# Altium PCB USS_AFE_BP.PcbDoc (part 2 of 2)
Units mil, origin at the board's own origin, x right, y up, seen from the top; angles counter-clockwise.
Board outline 2300 x 2500 mil, 4 copper layers (Top Layer, GND, PWR, Bottom Layer), stack 59 mil thick; 119 components, 70 nets, 303 pads, 68 vias.
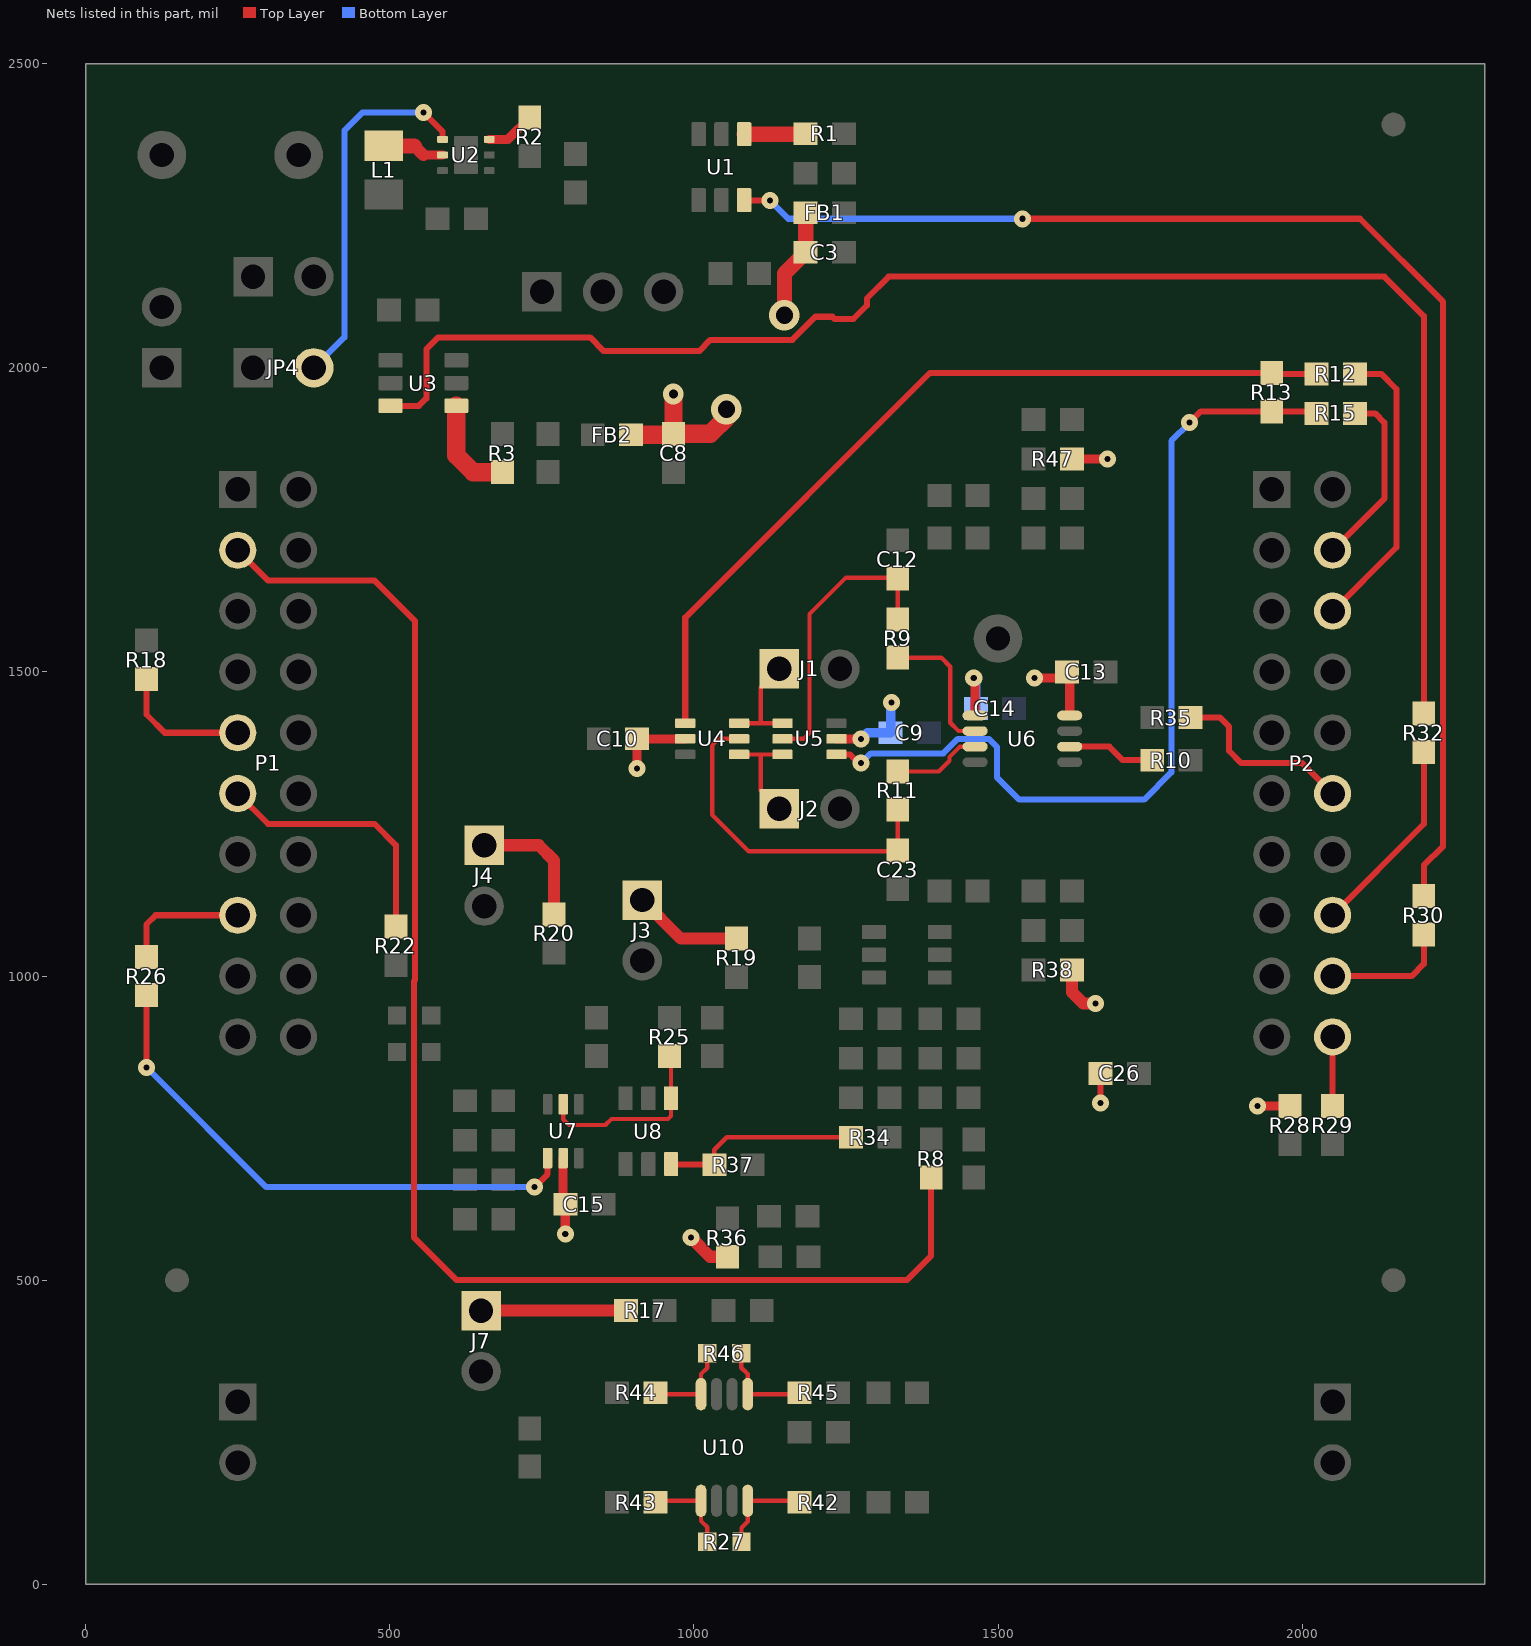
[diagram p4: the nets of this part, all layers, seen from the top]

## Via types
v1: diameter 28, hole 10, Top Layer to Bottom Layer, tented both sides, 55 vias
v2: diameter 34, hole 15, Top Layer to Bottom Layer, tented both sides, 7 vias
v3: diameter 50, hole 28, Top Layer to Bottom Layer, tented both sides, 4 vias
v4: diameter 19.68, hole 7.87, Top Layer to Bottom Layer, 2 vias

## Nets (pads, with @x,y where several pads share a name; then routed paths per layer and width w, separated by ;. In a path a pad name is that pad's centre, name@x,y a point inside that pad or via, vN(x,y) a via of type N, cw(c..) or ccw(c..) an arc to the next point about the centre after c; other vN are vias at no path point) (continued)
NetJ1_1: J1.1 U4.6 U5.4 | length 173.3
  Top Layer w7: U4.6@1074.29,1415.59 1110,1415.59 ; J1.1@1140,1505 1110,1475 1110,1415.59 ; U5.4@1145.71,1415.59 1110,1415.59
NetJ2_1: J2.1 U4.4 U5.6 | length 173.3
  Top Layer w7: U4.4@1074.29,1364.41 1110,1364.41 ; J2.1@1140,1275 1110,1305 1110,1364.41 ; U5.6@1145.71,1364.41 1110,1364.41
NetJP4_2: JP4.2 U2.4 | length 610.6
  Top Layer w10: v1(555.18,2419.88) 586.79,2388.27 U2.4@586.79,2375.48
  Bottom Layer w10: JP4.2@375.18,1999.88 425.18,2049.88 425.18,2389.88 455.18,2419.88 v1(555.18,2419.88)
NetL1_1: L1.1 U2.5 | length 102.8
  Top Layer w15: 555.18,2349.88 U2.5@586.79,2349.88
  Top Layer w20: 540.18,2364.88 555.18,2349.88
  Top Layer w25: L1.1@490.18,2364.88 540.18,2364.88
NetP1_3: P1.3 R8.1 | length 2378
  Top Layer w10: P1.3@250,1700 300,1650 475,1650 541.57,1583.43 541.57,993.49 540,991.91 540,570 610,500 1350,500 1390,540 R8.1@1390,668.5
NetP1_9: P1.9 R18.2 | length 220.9
  Top Layer w10: R18.2@100,1488.5 100,1430 130,1400 P1.9@250,1400
NetP1_11: P1.11 R22.2 | length 428.7
  Top Layer w10: P1.11@250,1300 300,1250 475,1250 510,1215 R22.2@510,1081.5
NetP1_15: P1.15 R26.2 | length 209.7
  Top Layer w10: R26.2@100,1031.5 100,1085 115,1100 P1.15@250,1100
NetP2_4: P2.4 R15.1 | length 299.9
  Top Layer w10: P2.4@2050,1700 2135,1785 2135,1910 2120,1925 R15.1@2086.5,1925
NetP2_6: P2.6 R12.1 | length 487.4
  Top Layer w10: P2.6@2050,1600 2155,1705 2155,1965 2130,1990 R12.1@2086.5,1990
NetP2_12: P2.12 R35.2 | length 318.7
  Top Layer w10: R35.2@1816.5,1425 1865,1425 1880,1410 1880,1370 1900,1350 2000,1350 P2.12@2050,1300 P2.12@2040,1300
NetP2_16: P2.16 R32.2 | length 330.6
  Top Layer w10: P2.16@2050,1100 2200,1250 R32.2@2200,1368.5
NetP2_18: P2.18 R30.2 | length 206.8
  Top Layer w10: P2.18@2050,1000 2180,1000 2200,1020 R30.2@2200,1068.5
NetP2_20: P2.20 R29.2 | length 113.5
  Top Layer w10: R29.2@2050,786.5 P2.20@2050,900
NetR1_2: R1.2 U1.1 | length 100.2
  Top Layer w25: U1.1@1082.58,2384.02 R1.2@1182.81,2384.02
NetR2_2: R2.2 U2.3 | length 81.5
  Top Layer w15: U2.3@663.56,2375.48 694.27,2375.48 R2.2@730.18,2411.38
NetR3_2: R3.2 U3.1 | length 168.9
  Top Layer w30: U3.1@609.31,1937.48 609.31,1855.75 636.67,1828.39 R3.2@685.18,1828.39
NetR9_1: R9.1 U6.2 | length 231.3
  Top Layer w7: R9.1@1335,1523.5 1406.5,1523.5 1421.37,1508.63 1421.37,1416.34 1434.92,1402.8 U6.2@1462.24,1402.8
NetR10_1: R10.1 U6.6 | length 144.9
  Top Layer w10: U6.6@1617.76,1377.2 1682.8,1377.2 1705,1355 R10.1@1753.5,1355
NetR11_1: R11.1 U6.3 | length 148.9
  Top Layer w7: R11.1@1335,1336.5 1402.5,1336.5 1420,1354 1420,1360 1437.2,1377.2 U6.3@1462.24,1377.2
  Top Layer w10: U6.3@1462.24,1377.2 U6.3@1462.24,1378.49
NetR25_2: R25.2 U7.5 U8.4 | length 308.8
  Top Layer w7: U7.5@785,789.29 785,764.68 794.68,755 855,755 855,755.71 864.29,765 957.4,765 962.4,770 U8.4@962.4,799.13 R25.2@962.4,866.1
NetR27_1: R27.1 R42.2 U10.8 | length 157.8
  Top Layer w7: R27.1@1078,70 1078,93 1088.38,103.38 U10.8@1088.38,137.4 1171.1,137.4 R42.2@1173.5,135
NetR27_2: R27.2 R43.1 U10.5 | length 147.8
  Top Layer w7: R43.1@936.5,135 938.9,137.4 U10.5@1011.61,137.4 1011.61,104.37 1022,93.99 R27.2@1022,70
NetR34_1: R34.1 R37.2 U8.3 | length 329.5
  Top Layer w7: R37.2@1033.5,690 1033.5,714.5 1054,735 R34.1@1258.5,735
  Top Layer w10: U8.3@962.4,690.87 963.27,690 R37.2@1033.5,690
NetR44_1: R44.1 R46.2 U10.4 | length 147.8
  Top Layer w7: R44.1@936.5,315 938.9,312.6 U10.4@1011.61,312.6 1011.61,345.63 1021.87,355.89 R46.2@1021.87,380
NetR45_2: R45.2 R46.1 U10.1 | length 157.9
  Top Layer w7: R46.1@1077.87,380 1077.87,356.15 1088.38,345.63 U10.1@1088.38,312.6 1171.1,312.6 R45.2@1173.5,315
RX_GAIN: R26.1 U7.1 | length 894.7
  Top Layer w10: v1(100,850) R26.1@100,968.5 ; v1(738,653) 759.41,674.41 U7.1@759.41,700.71
  Bottom Layer w10: v1(100,850) 297,653 v1(738,653)
RX_MUX: R12.2 R13.1 U4.1 | length 1378.7
  Top Layer w10: U4.1@985.71,1415.59 985.71,1589.29 1387.91,1991.5 R13.1@1950,1991.5 1951.5,1990 R12.2@2023.5,1990
RX_PWRSW: R32.1 U3.6 | length 2542.8
  Top Layer w10: U3.6@501.04,1937.48 547.77,1937.48 560.18,1949.88 560.18,2030.75 579.31,2049.88 829.29,2049.88 851.67,2027.51 1008.69,2027.51 1027.06,2045.88 1161.75,2045.88 1199.75,2083.88 1227.61,2083.88 1230.98,2080.51 1262.36,2080.51 1284.55,2102.7 1284.55,2114.25 1320.18,2149.88 2135.12,2149.88 2200,2085 R32.1@2200,1431.5
RX_SIGNAL: C23.1 R11.2 U4.5 | length 560.9
  Top Layer w7: U4.5@1074.29,1390 1040,1390 1030,1380 1030,1265 1090,1205 1333.5,1205 C23.1@1335,1206.5 R11.2@1335,1273.5
TX_MUX: R13.2 R15.2 U5.1 | length 1468.5
  Top Layer w10: U5.1@1234.88,1365 U5.1@1234.29,1364.41 1256.46,1364.41 1270.87,1350 v1(1275,1350) ; v1(1815,1910) 1833.5,1928.5 R13.2@1950,1928.5 2020,1928.5 R15.2@2023.5,1925
  Bottom Layer w10: v1(1275,1350) 1291.02,1366.02 1410,1366.02 1433.98,1390 1485,1390 1498.13,1376.87 1498.13,1326.87 1535,1290 1740,1290 1785,1335 1785,1880 v1(1815,1910)
TX_PWRSW: R30.1 U1.6 | length 2207.1
  Top Layer w10: U1.6@1083.44,2274.88 v1(1125.18,2274.88) ; v1(1540,2245) 2095,2245 2231.57,2108.43 2231.57,1213.49 2200,1181.91 R30.1@2200,1131.5
  Bottom Layer w10: v1(1125.18,2274.88) 1155.06,2245 v1(1540,2245)
TX_SIGNAL: C12.1 R9.2 U5.5 | length 478.8
  Top Layer w7: U5.5@1145.71,1390 1180,1390 1190,1400 1190,1595 1250,1655 C12.1@1333.5,1655 ; R9.2@1335,1586.5 C12.1@1335,1653.5
VCC-RX: C8.1 C13.2 C15.1 C26.2 FB2.2 J3.1 J4.1 J7.1 R17.2 R19.2 R20.2 R28.1 R36.2 R38.2 R47.2 U6.8 U7.2 | length 1446.4
  Top Layer w10: v1(1668.5,791.5) C26.2@1668.5,840
  Top Layer w15: C15.1@785,628.5 U7.2@785,700.71 ; v1(788.5,575.98) C15.1@788.5,625 ; v1(1560,1490) 1603.5,1490 C13.2@1613.5,1500 1617.76,1495.75 U6.8@1617.76,1428.39 ; R47.2@1621.5,1850 v1(1680,1850) ; v1(1926.5,786.5) R28.1@1980,786.5
  Top Layer w20: J7.1@650,450 R17.2@888.5,450 ; J4.1@655,1215 745,1215 770,1190 R20.2@770,1101.5 ; J3.1@915,1125 978.5,1061.5 R19.2@1070,1061.5 ; v1(995,570) 1026.5,538.5 R36.2@1055,538.5 ; R38.2@1621.5,1008.68 1621.5,973.5 1640,955 v1(1660,955)
  Top Layer w30: FB2.2@896.67,1889.88 C8.1@964.98,1889.88 ; v2(966.18,1956.88) 966.47,1956.59 C8.1@966.47,1891.38 1026.67,1891.38 1053.18,1917.88 v3(1053.18,1931.88)
VCC-TX: C3.1 C9.1 C10.1 C14.1 FB1.2 U4.2 U5.2 U6.1 | length 572.2
  Top Layer w15: v1@904,1339 v1(906.5,1341.5) C10.1@906.5,1390 U4.2@985.71,1390 ; U5.2@1234.29,1390 v1(1275,1390) ; v1(1460,1490) 1462.24,1487.76 U6.1@1462.24,1428.39
  Top Layer w25: v3(1148.68,2086.38) 1148.68,2154.88 C3.1@1183.68,2189.88 FB1.2@1183.68,2254.88
  Bottom Layer w15: v1(1275,1390) 1285,1400 C9.1@1323.5,1400 1323.5,1448.5 v1(1325,1450) ; v1(1460,1490) 1463.5,1486.5 C14.1@1463.5,1440
pads on no net: FID1.1 FID2.1 FID3.1 LBL1.0 P1.5 P1.6 P1.7 P1.8 P1.10 P1.12 P1.13 P1.17 P1.18 P1.19 P1.20 P2.1 P2.3 P2.5 P2.7 P2.8 P2.9 P2.10 P2.11 P2.13 P2.14 P2.15 P2.17 P2.19 U1.3 U2.7@625.18,2332.17 U2.7@625.18,2367.6 U3.3

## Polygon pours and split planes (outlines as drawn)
VCC-RX on PWR "VCC-RX_L03_P012" (solid, remove dead copper, pour order 12): 25.26,2475 2274.74,2475 2274.74,25.26 25.26,25.26
VCC-TX on PWR "VCC-TX_L03_P010" (solid, remove dead copper, pour order 10): 807.5,1300 1510,1300 1510,1600 1510,2140 1100,2140 1100,1600 807.5,1600
GND on GND "GND_L02_P002" (solid, pour order 2): 25,2475 2275,2475 2275,25 25,25

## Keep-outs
Keep-Out Layer:
  pour cut-out: 1267.3,1185 1267.3,975 1432.68,975 1435,977.32 1435,1185
  pour cut-out: 1340,973.98 1340,836.46 1478.71,836.46 1480,837.75 1480,975 1341.02,975
  pour cut-out: 854.13,827.68 854.13,662.32 985,662.32 985,827.68
  pour cut-out: 985,725 1070,725 1070,661.46 985,661.46
  pour cut-out: 935,827.68 935,900 985,900 985,827.68
  pour cut-out: 905,355 905,270 1200,270 1200,355
  pour cut-out: 905,175 905,95 1205,95 1205,175
  pour cut-out: 997.87,404 997.87,355 1101.87,355 1101.87,404
  pour cut-out: 998,95 998,46 1102,46 1102,95
  pour cut-out: 1363.54,1185 1363.54,1295 1300,1295 1300,1220 1218.58,1220 1218.58,1555 1100.99,1555 1010,1484.86 1010,1260 1085,1185
  pour cut-out: 1300,1680 1300,1825 1430,1825 1430,1680
  lines w15: -7.5,0 ccw(c0,0) 0,-7.5 ; -7.5,0 ccw(c0,0) 0,-7.5 ; -7.5,0 -7.5,2500 ; -7.5,2500 cw(c0,2500) 0,2507.5 ; -7.5,2500 cw(c0,2500) 0,2507.5 ; 0,-7.5 2300,-7.5 ; 0,2507.5 2300,2507.5 ; 2300,-7.5 ccw(c2300,0) 2307.5,0 ; 2300,-7.5 ccw(c2300,0) 2307.5,0 ; 2300,2507.5 cw(c2300,2500) 2307.5,2500 ; 2300,2507.5 cw(c2300,2500) 2307.5,2500 ; 2307.5,0 2307.5,2500
  text ".Layer_Name" at 577,-858.49 h60

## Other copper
Top Layer:
  text ".Layer_Name" at 577,-858.49 h60
GND:
  pour cut-out: 1170,1555 1170,1600 1250,1680 1363.54,1680 1363.54,1565 1300,1565 1300,1630 1295,1635 1250,1635 1220,1605 1220,1555
  text ".Layer_Name" at 577,-858.49 h60
PWR:
  pour cut-out: 1170,1555 1170,1600 1250,1680 1363.54,1680 1363.54,1565 1300,1565 1300,1630 1295,1635 1250,1635 1220,1605 1220,1555
  text ".Layer_Name" at 577,-858.49 h60
Bottom Layer:
  text ".Layer_Name" at 577,-858.49 h60

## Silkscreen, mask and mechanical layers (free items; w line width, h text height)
Top Overlay:
  lines w10: 965,1290 1030,1290 1085,1345 1140,1345
  text "3V3" at 75.18,2424.88 h40
  text "GND" at 300.18,2424.88 h40
  text "USS-AFE-BP" at 1590,2380 h40
  text ".PCB_Rev" at 1615,2300 h40
  text "5VTX" at 321.18,2213.88 h30
  text "|5VTX|" at 845.18,2194.88 h30
  text "|3V3TX|" at 700.18,2014.88 h30
  text "5VTX" at 330,1900 h30
  text "1" at 155,1780 h40
  text "21" at 400.01,1780 h40
  text "40" at 1835,1780 h40
  text "20" at 2100,1780 h40
  text "2" at 170,1685 h40
  text "22" at 400.01,1685 h40
  text "39" at 1840,1680 h40
  text "19" at 2100,1680 h40
  text "3" at 170,1580 h40
  text "23" at 400,1580 h40
  text "38" at 1840,1580 h40
  text "18" at 2100,1580 h40
  text "X1" at 1100,1565 h60
  text "GND" at 1180,1565 h60
  text "4" at 170,1480 h40
  text "24" at 400,1480 h40
  text "17" at 2100,1480 h40
  text "37" at 1900.01,1475 h40 r90
  text "5" at 170,1380 h40
  text "25" at 400,1380 h40
  text "16" at 2100,1380 h40
  text "36" at 1900.01,1370 h40 r90
  text "6" at 170,1280 h40
  text "26" at 400,1280 h40
  text "15" at 2100,1280 h40
  text "35" at 1905,1265 h40 r90
  text "7" at 170,1185 h40
  text "27" at 400,1185 h40
  text "34" at 1840,1180 h40
  text "14" at 2100,1180 h40
  text "X2" at 1110,1175 h60
  text "GND" at 1180,1175 h60
  text "8" at 170,1080 h40
  text "28" at 400,1080 h40
  text "33" at 1840,1080 h40
  text "13" at 2100,1080 h40
  text "9" at 170,980 h40
  text "29" at 395,980 h40
  text "32" at 1840,980 h40
  text "12" at 2100,980 h40
  text "10" at 140,880 h40
  text "30" at 395,880 h40
  text "31" at 1840,880 h40
  text "11" at 2100,880 h40
  text "GND" at 2130,285 h40
  text "GND" at 60,280 h40
  text "J5" at 310,230 h72.83
  text "J6" at 1920,230 h72.83
  text "GND" at 65,185 h40
  text "GND" at 2130,170 h40
  text ".Layer_Name" at 577,-858.49 h60
Bottom Overlay:
  text ".Layer_Name" at 577,-858.49 h60
Top Paste:
  text ".Layer_Name" at 577,-858.49 h60
Bottom Paste:
  text ".Layer_Name" at 577,-858.49 h60
Top Solder:
  text ".Layer_Name" at 577,-858.49 h60
  text ".Layer_Name" at 577,-858.49 h60
Bottom Solder:
  text ".Layer_Name" at 577,-858.49 h60
Drill Guide:
  text ".Layer_Name" at 577,-858.49 h60
M1 Board Outline:
  the board outline again, w10
  text ".Layer_Name" at 577,-858.49 h60
M2 Board Dimensions:
  rectangle: 125,-400 500,-275
  rectangle: 0,-275 125,-150
  lines w7: 0,-275 1000,-275 ; 125,-400 125,-150 ; 250,-400 250,-150 ; 500,-400 500,-150 ; 750,-400 750,-150 ; 0,-400 0,-150 1000,-150 1000,-400 0,-400
  text ".Layer_Name" at 577,-858.49 h60
M3 3D STEP Top:
  text ".Layer_Name" at 577,-858.49 h60
M4 3D STEP Bottom:
  text ".Layer_Name" at 577,-858.49 h60
M5 Assembly Top:
  lines w10: -292,-930.17 6308,-930.17 ; -292,-726.83 6310,-726.83 ; -292,-523.5 -292,-1133.5 3713,-1133.5 6310,-1133.5 6310,-523.5 -291.5,-523.5 -291.5,-1133.5 1284,-1133.5 ; 2173,-1133.5 2173,-523.5 ; 3440,-726.83 3440,-523.5 ; 4280,-726.83 4280,-523.5 ; 4902,-1140 4902,-937.17
  text "COMPONENTS MARKED 'DNP' SHOULD NOT BE POPULATED." at 1153.5,-318.5 h60
  text "ASSEMBLY VARIANT:" at 1153,-434 h60
  text ".VariantName" at 2189,-434 h60
  text "PCB VIEWED FROM TOP SIDE" at -228.5,-655.67 h60
  text "BOARD #:" at 2248,-655.67 h60
  text ".PRJ_Number" at 2793.5,-655.67 h60
  text "REV:" at 3638,-655.67 h60
  text ".PCB_Rev" at 3929.5,-655.67 h60
  text "SVN REV:" at 4476,-655.67 h60
  text ".VersionControl_RevNumber" at 4982,-655.67 h60
  text "TID #:" at 2248,-859 h60
  text ".TID" at 2793.5,-859 h60
  text "PLOT NAME =" at -228.5,-1064.34 h60
  text ".plot_File_Name" at 577,-1064.34 h60
  text "GENERATED    :" at 2250,-1064.34 h60
  text ".Print_Date" at 3119.5,-1064.34 h60
  text ".Print_Time" at 3848.5,-1064.34 h60
  text "TEXAS INSTRUMENTS" at 5113,-1064.34 h60
M6 Assembly Bottom:
  lines w10: -292.5,-727.33 6309.5,-727.33 ; -290.5,-930.67 6309.5,-930.67 ; 1115.5,-1140.5 1115.5,-937.67 ; 1737.5,-727.33 1737.5,-524 ; 2577.5,-727.33 2577.5,-524 ; 3844.5,-1134 3844.5,-524 ; 4733.5,-1134 6309,-1134 6309,-524 -292.5,-524 -292.5,-1134 2304.5,-1134 6309.5,-1134 6309.5,-524
  text "COMPONENTS MARKED 'DNP' SHOULD NOT BE POPULATED." at 6102,-318 h60
  text ".VariantName" at 5058,-434 h60
  text "ASSEMBLY VARIANT:" at 6097,-434 h60
  text ".VersionControl_RevNumber" at 1035.5,-656.17 h60
  text "SVN REV:" at 1541.5,-656.17 h60
  text ".PCB_Rev" at 2088,-656.17 h60
  text "REV:" at 2379.5,-656.17 h60
  text ".PRJ_Number" at 3224,-656.17 h60
  text "BOARD #:" at 3769.5,-656.17 h60
  text "PCB VIEWED FROM BOTTOM SIDE" at 6246,-656.17 h60
  text ".TID" at 3224,-859.5 h60
  text "TID #:" at 3769.5,-859.5 h60
  text "TEXAS INSTRUMENTS" at 904.5,-1064.84 h60
  text ".Print_Time" at 2169,-1064.84 h60
  text ".Print_Date" at 2898,-1064.84 h60
  text "GENERATED    :" at 3767.5,-1064.84 h60
  text ".plot_File_Name" at 5440.5,-1064.84 h60
  text "PLOT NAME =" at 6246,-1064.84 h60
M9 Title Sheet:
  drawing of 57 lines, arcs and shapes, not listed
  text "1" at 739.84,8036.5 h70
  text "2" at 3235.5,8036.5 h70
  text "3" at 5724.84,8036.5 h70
  text "4" at 8231.51,8036.5 h70
  text "5" at 10730.5,8036.5 h70
  text "6" at 13235.5,8036.5 h70
  text "A" at -416.5,6893.5 h70
  text "A" at 14383.5,6893.5 h70
  text "B" at -416.5,4513.5 h70
  text "B" at 14383.5,4513.5 h70
  text "C" at -416.5,2138.5 h70
  text "C" at 14383.5,2138.5 h70
  text "PROJECT TITLE:" at 11343.5,277.5 h45
  text ".PRJ_Title" at 11393.5,144.17 h70
  text "DESIGNED FOR:" at 11343.5,-23.5 h45
  text ".PRJ_Customer" at 11393.5,-163.5 h70
  text "D" at -416.5,-231.5 h70
  text "D" at 14383.5,-231.5 h70
  text "FILE NAME:" at 11343.5,-323.5 h45
  text ".PCB_File_Name_No_Path" at 11393.5,-443.5 h70
  text "Texas Instruments (TI) and/or its licensors do not warrant the accuracy or completeness of this specification" at 6374,-605.34 h45
  text "ENGINEER:" at 11343.5,-613.5 h45
  text "LAYOUT BY:" at 12848.5,-613.5 h45
  text "or any information contained therein. TI and/or its licensors do not warrant that this design will meet" at 6329.01,-718 h45
  text ".PRJ_Engineer" at 11393.5,-768.49 h70
  text ".PCB_Layout" at 12899,-768.49 h70
  text "the specifications, will be suitable for your application or fit for any particular purpose, or will operate in" at 6329.01,-830.67 h45
  text ".Layer_Name" at 577,-858.49 h60
  text "ALTIUM DESIGNER VERSION:" at 12848.5,-923.5 h45
  text "an implementation. TI and/or its licensors do not warrant that the design is production worthy. You should" at 6329.01,-943.33 h45
  text "completely validate and test your design implementation to confirm the system functionality for your application." at 6374,-1056 h45
  text ".print_Scale" at 11393.5,-1056.83 h70
  text ".Application_BuildNumber" at 12899,-1056.83 h70
  text "1" at 739.84,-1263.5 h70
  text "2" at 3235.5,-1263.5 h70
  text "3" at 5724.84,-1263.5 h70
  text "4" at 8231.51,-1263.5 h70
  text "5" at 10730.5,-1263.5 h70
  text "6" at 13235.5,-1263.5 h70
M10 Fab Notes:
  drawing of 185 lines, arcs and shapes, not listed
  text "DESIGN INFORMATION" at 12381.02,5910 h60
  text "MIN. TRACK WIDTH:" at 11736.46,5730 h60
  text "7" at 12832.7,5730 h60
  text "MIL" at 12987.46,5730 h60
  text "MIN. CLEARANCE:" at 11736.46,5598 h60
  text "0.2" at 12772.7,5598 h60
  text "mm" at 12987.46,5598 h60
  text "MIN. VIA PAD SIZE:" at 11736.46,5466 h60
  text "24" at 12802.71,5466 h60
  text "MIL" at 12987.46,5466 h60
  text "0.05mm (2MIL)" at 12431.46,5324.29 h60
  text "MINIMUM ANNULAR RING" at 11407.23,5320 h60
  text "EXTERNAL" at 13139.46,5320 h60
  text "PER" at 11607.23,5202 h60
  text "IPC-D-275 CLASS 2 LEVEL C" at 11827.23,5202 h60
  text "MIL, HOLES" at 13315.46,5089.71 h60
  text "+/-" at 12923,5089 h60
  text "+/-" at 13777,5089 h60
  text "REGISTRATION TOLERANCES:" at 11407.23,5084 h60
  text "METAL" at 12607,5084 h60
  text "5" at 13183.2,5084 h60
  text "3" at 14016.2,5084 h60
  text "MIL" at 14132.46,5084 h60
  text "MATERIAL:" at 11332.46,4874.54 h60
  text "FR-4 High Tg" at 12318.9,4734.21 h60
  text "FR-408" at 11753.46,4725.64 h60
  text "X" at 12165.46,4725.64 h60
  text "OTHER" at 13241.46,4725.64 h60
  text "62 MIL (1.6mm) +/-10%" at 12073.56,4562.92 h60
  text "THICKNESS:" at 11407.23,4558.64 h60
  text "X" at 11945.4,4558.64 h60
  text "OTHER" at 13358.46,4558.64 h60
  text "TOLERANCE:" at 11407.23,4400.64 h60
  text "X" at 12246.53,4400.64 h60
  text "ANSI IPC-6012 TYPE 3 CLASS 2" at 12433.48,4400.64 h60
  text "OTHER +/-" at 12433.46,4244.64 h60
  text "BOW & TWIST:" at 11407.23,4087.64 h60
  text "X" at 12246.53,4087.64 h60
  text "ANSI IPC-6012 TYPE 3 CLASS 2" at 12433.48,4087.64 h60
  text "OTHER +/-" at 12433.46,3929.13 h60
  text "DRILLING:" at 11332.46,3790.64 h60
  text "REFERENCE:" at 11407.23,3673.64 h60
  text "X" at 12055.46,3673.64 h60
  text "AS SHOWN" at 12242.46,3673.64 h60
  text "X" at 12956.46,3673.64 h60
  text "NC_DRILL FILES" at 13093.46,3673.64 h60
  text "PTH MIN COPPER THICKNESS:" at 11407.23,3515.64 h60
  text "X" at 12757.46,3515.64 h60
  text "1MIL" at 12894.46,3515.64 h60
  text "OTHER" at 13391.46,3515.64 h60
  text "BOARD FINISH:" at 11332.46,3356.64 h60
  text "SILKSCREEN:" at 11487.68,3238.64 h60
  text "X" at 12436.46,3238.64 h60
  text "TOP" at 12562.46,3238.64 h60
  text "X" at 12946.46,3238.64 h60
  text "BOTTOM" at 13073.46,3238.64 h60
  text "SILKSCREEN COLOR:" at 11487.68,3071.64 h60
  text "X" at 12435.42,3071.64 h60
  text "WHITE" at 12562.46,3071.64 h60
  text "OTHER" at 13073.46,3071.64 h60
  text "SOLDER RESIST COLOR:" at 11487.68,2901.64 h60
  text "GREEN" at 12182.46,2742.44 h60
  text "BLUE" at 12773.46,2742.44 h60
  text "RED" at 13311.46,2742.44 h60
  text "X" at 12650,2735 h60
  text "IMMERSION GOLD (ENIG)" at 12393.46,2553.92 h60
  text "ENEPIG" at 13731,2550.64 h60
  text "SURFACE FINISH:" at 11332.46,2549.64 h60
  text "X" at 12206.51,2549.64 h60
  text "IMM. TIN/SILVER OR EQUIV" at 11662,2392.64 h60
  text "OTHER" at 13093.46,2392.64 h60
  text "ARRAY/PANEL:" at 11332.46,2213.64 h60
  text "CUT AND TRIM PER MECH LAYER 1" at 12393.46,2209.35 h60
  text "N.C. ROUTE" at 12393.46,2057.64 h60
  text "X" at 13072.46,2057.64 h60
  text "V. SCORE" at 13259.46,2057.64 h60
  text "CERTIFICATION:" at 11332.46,1920.64 h60
  text "MATERIALS AND WORKMANSHIP FOR ALL PCBS" at 12057.46,1920.64 h60
  text "TO MEET OR EXCEED THE REQUIREMENTS OF:" at 12057.46,1822.64 h60
  text "X" at 11683.96,1686.13 h60
  text "ANSI IPC-A-600F CLASS ->" at 11822.96,1686.13 h60
  text "X" at 13462.02,1686.13 h60
  text "2" at 13580.96,1686.14 h60
  text "1" at 13265.96,1684.64 h60
  text "3" at 13934.96,1684.64 h60
  text "X" at 11686.02,1526.64 h60
  text "UL 94V-0" at 11822.96,1526.64 h60
  text "X" at 12498.02,1526.64 h60
  text "RoHS" at 12634.96,1526.64 h60
  text "OTHER" at 13279.36,1526.64 h60
  text "PER ORDER" at 13676.42,1526.64 h60
  text "ADDITIONAL REQUIREMENTS:" at 11332.46,1385.64 h60
  text "MICROSECTION:" at 11407.23,1270.64 h60
  text "YES" at 12312.96,1270.64 h60
  text "REQUIRED" at 13174.46,1114.49 h60
  text "BARE BOARD ELEC. TEST:" at 11407.23,1111.64 h60
  text "NONE" at 12712.96,1111.64 h60
  text "X" at 13047.46,1111.64 h60
  text "PER ORDER" at 13766.46,1111.64 h60
  text "MANUFACTURER'S UL:" at 11407.23,954.64 h60
  text "RAIL" at 12572.96,950.35 h60
  text "METAL" at 13064.77,950.35 h60
  text "X" at 13440,950 h60
  text "SILK" at 13576.46,950.35 h60
  text ".Layer_Name" at 577,-858.49 h60
M11 Gerber Information:
  lines w10: -292,-930.17 6308,-930.17 ; -292,-726.83 6310,-726.83 ; -292,-523.5 -292,-1133.5 3713,-1133.5 6310,-1133.5 6310,-523.5 -291.5,-523.5 -291.5,-1133.5 1284,-1133.5 ; 2173,-1133.5 2173,-523.5 ; 3440,-726.83 3440,-523.5 ; 4280,-726.83 4280,-523.5 ; 4902,-1140 4902,-937.17
  text "ALL ARTWORK VIEWED FROM TOP SIDE" at -228.5,-655.67 h60
  text "BOARD #:" at 2248,-655.67 h60
  text ".PRJ_Number" at 2793.5,-655.67 h60
  text "REV:" at 3638,-655.67 h60
  text ".PCB_Rev" at 3929.5,-655.67 h60
  text "SVN REV:" at 4476,-655.67 h60
  text ".VersionControl_RevNumber" at 4982,-655.67 h60
  text "LAYER NAME =" at -228.5,-858.49 h60
  text "TID #:" at 2248,-859 h60
  text ".TID" at 2793.5,-859 h60
  text "PLOT NAME =" at -228.5,-1064.34 h60
  text ".plot_File_Name" at 577,-1064.34 h60
  text "GENERATED    :" at 2250,-1064.34 h60
  text ".Print_Date" at 3119.5,-1064.34 h60
  text ".Print_Time" at 3848.5,-1064.34 h60
  text "TEXAS INSTRUMENTS" at 5113,-1064.34 h60
M12 Stackup:
  drawing of 295 lines, arcs and shapes, not listed
  text "Layer" at 9790.34,7830 h60
  text "Name" at 10200.26,7830 h60
  text "Material" at 11130,7830 h60
  text "Thickness" at 11989.77,7830 h60
  text "Constant" at 12639.6,7830 h60
  text "Board Layer Stack" at 13209.46,7830 h60
  text "1" at 9790.34,7710 h60
  text "Top Overlay" at 10200.26,7710 h60
  text "2" at 9790.34,7590 h60
  text "Top Solder" at 10200.26,7590 h60
  text "Solder Resist" at 11130,7590 h60
  text "0.40mil" at 11989.77,7590 h60
  text "3.5" at 12639.6,7590 h60
  text "3" at 9790.34,7470 h60
  text "Top Layer" at 10200.26,7470 h60
  text "Copper" at 11130,7470 h60
  text "0.70mil" at 11989.77,7470 h60
  text "4" at 9790.34,7350 h60
  text "Dielectric1" at 10200.26,7350 h60
  text "FR-4" at 11130,7350 h60
  text "7.60mil" at 11989.77,7350 h60
  text "4.8" at 12639.6,7350 h60
  text "5" at 9790.34,7230 h60
  text "GND" at 10200.26,7230 h60
  text "Copper" at 11130,7230 h60
  text "1.20mil" at 11989.77,7230 h60
  text "6" at 9790.34,7110 h60
  text "Dielectric 3" at 10200.26,7110 h60
  text "40.00mil" at 11989.77,7110 h60
  text "4.2" at 12639.6,7110 h60
  text "7" at 9790.34,6990 h60
  text "PWR" at 10200.26,6990 h60
  text "Copper" at 11130,6990 h60
  text "1.20mil" at 11989.77,6990 h60
  text "8" at 9790.34,6870 h60
  text "Dielectric 2" at 10200.26,6870 h60
  text "7.60mil" at 11989.77,6870 h60
  text "4.2" at 12639.6,6870 h60
  text "9" at 9790.34,6750 h60
  text "Bottom Layer" at 10200.26,6750 h60
  text "Copper" at 11130,6750 h60
  text "0.70mil" at 11989.77,6750 h60
  text "10" at 9790.34,6630 h60
  text "Bottom Solder" at 10200.26,6630 h60
  text "Solder Resist" at 11130,6630 h60
  text "0.40mil" at 11989.77,6630 h60
  text "3.5" at 12639.6,6630 h60
  text "11" at 9790.34,6510 h60
  text "Bottom Overlay" at 10200.26,6510 h60
  text ".Layer_Name" at 577,-858.49 h60
M13 Component Bodies Top:
  text ".Layer_Name" at 577,-858.49 h60
M14 Component Bodies Bottom:
  text ".Layer_Name" at 577,-858.49 h60
M15 Courtyards Top:
  text ".Layer_Name" at 577,-858.49 h60
M16 Courtyards Bottom:
  text ".Layer_Name" at 577,-858.49 h60
Drill Drawing:
  circle w10: c5683.72,2893.32 r16.58
  circle w10: c5683.72,2893.32 r27.63
  lines w10: 5656.09,2644.68 5683.72,2617.06 5711.34,2644.68 5683.72,2672.31 5656.09,2644.68 ; 5656.09,2741.38 5656.09,2755.19 5669.9,2769 5656.09,2782.82 5656.09,2796.63 5669.9,2796.63 5683.72,2782.82 5697.53,2796.63 5711.34,2796.63 5711.34,2782.82 5697.53,2769 5711.34,2755.19 5711.34,2741.38 5697.53,2741.38 5683.72,2755.19 5669.9,2741.38 5656.09,2741.38 ; 5656.09,2990.02 5711.34,2990.02 5711.34,3045.27 5656.09,3045.27 5656.09,2990.02 ; 5656.09,3169.59 5711.34,3169.59 5683.72,3114.34 5656.09,3169.59 ; 5656.09,3252.47 5669.9,3252.47 5683.72,3238.66 5697.53,3252.47 5711.34,3252.47 5697.53,3266.28 5711.34,3280.1 5697.53,3280.1 5683.72,3293.91 5669.9,3280.1 5656.09,3280.1 5669.9,3266.28 5656.09,3252.47 ; 5667.14,3001.07 5700.29,3001.07 5700.29,3034.22 5667.14,3034.22 5667.14,3001.07 ; 5667.14,3158.54 5700.29,3158.54 5683.72,3125.39 5667.14,3158.54 ; 5667.14,3257.99 5675.43,3257.99 5683.72,3249.71 5692.01,3257.99 5700.29,3257.99 5692.01,3266.28 5700.29,3274.57 5692.01,3274.57 5683.72,3282.86 5675.43,3274.57 5667.14,3274.57 5675.43,3266.28 5667.14,3257.99
  lines w12: 5606,2579.76 7584.02,2579.76 ; 5606,3325.68 7584.02,3325.68 ; 5943.86,2455.44 5943.86,3450 ; 6275.86,2455.44 6275.86,3450 ; 6912.43,2455.44 6912.43,3450 ; 7171.57,2455.44 7171.57,3450 ; 5606,2455.44 7584.02,2455.44 7584.02,3450 5606,3450 5606,2455.44
  text "Symbol" at 5680.59,3362.98 h72
  text "Quantity" at 5981.16,3362.98 h72
  text "Finished Hole Size" at 6313.16,3362.98 h72
  text "Plated" at 6949.72,3362.98 h72
  text "Hole Type" at 7208.86,3362.98 h72
  text "2" at 5981.16,3238.66 h60
  text "7.87mil (0.200mm)" at 6313.16,3238.66 h60
  text "PTH" at 6949.72,3238.66 h60
  text "Round" at 7208.86,3238.66 h60
  text "55" at 5981.16,3114.34 h60
  text "10.00mil (0.254mm)" at 6313.16,3114.34 h60
  text "PTH" at 6949.72,3114.34 h60
  text "Round" at 7208.86,3114.34 h60
  text "7" at 5981.16,2990.02 h60
  text "15.00mil (0.381mm)" at 6313.16,2990.02 h60
  text "PTH" at 6949.72,2990.02 h60
  text "Round" at 7208.86,2990.02 h60
  text "4" at 5981.16,2865.7 h60
  text "28.00mil (0.711mm)" at 6313.16,2865.7 h60
  text "PTH" at 6949.72,2865.7 h60
  text "Round" at 7208.86,2865.7 h60
  text "22" at 5981.16,2741.38 h60
  text "40.00mil (1.016mm)" at 6313.16,2741.38 h60
  text "PTH" at 6949.72,2741.38 h60
  text "Round" at 7208.86,2741.38 h60
  text "44" at 5981.16,2617.06 h60
  text "40.16mil (1.020mm)" at 6313.16,2617.06 h60
  text "PTH" at 6949.72,2617.06 h60
  text "Round" at 7208.86,2617.06 h60
  text "134 Total" at 5981.16,2492.74 h60
  text ".Layer_Name" at 577,-858.49 h60

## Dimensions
0,0 to 2300,0 on M2 Board Dimensions
0,0 to 0,2500 on M2 Board Dimensions
0,-400 to 1000,-400 on M2 Board Dimensions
